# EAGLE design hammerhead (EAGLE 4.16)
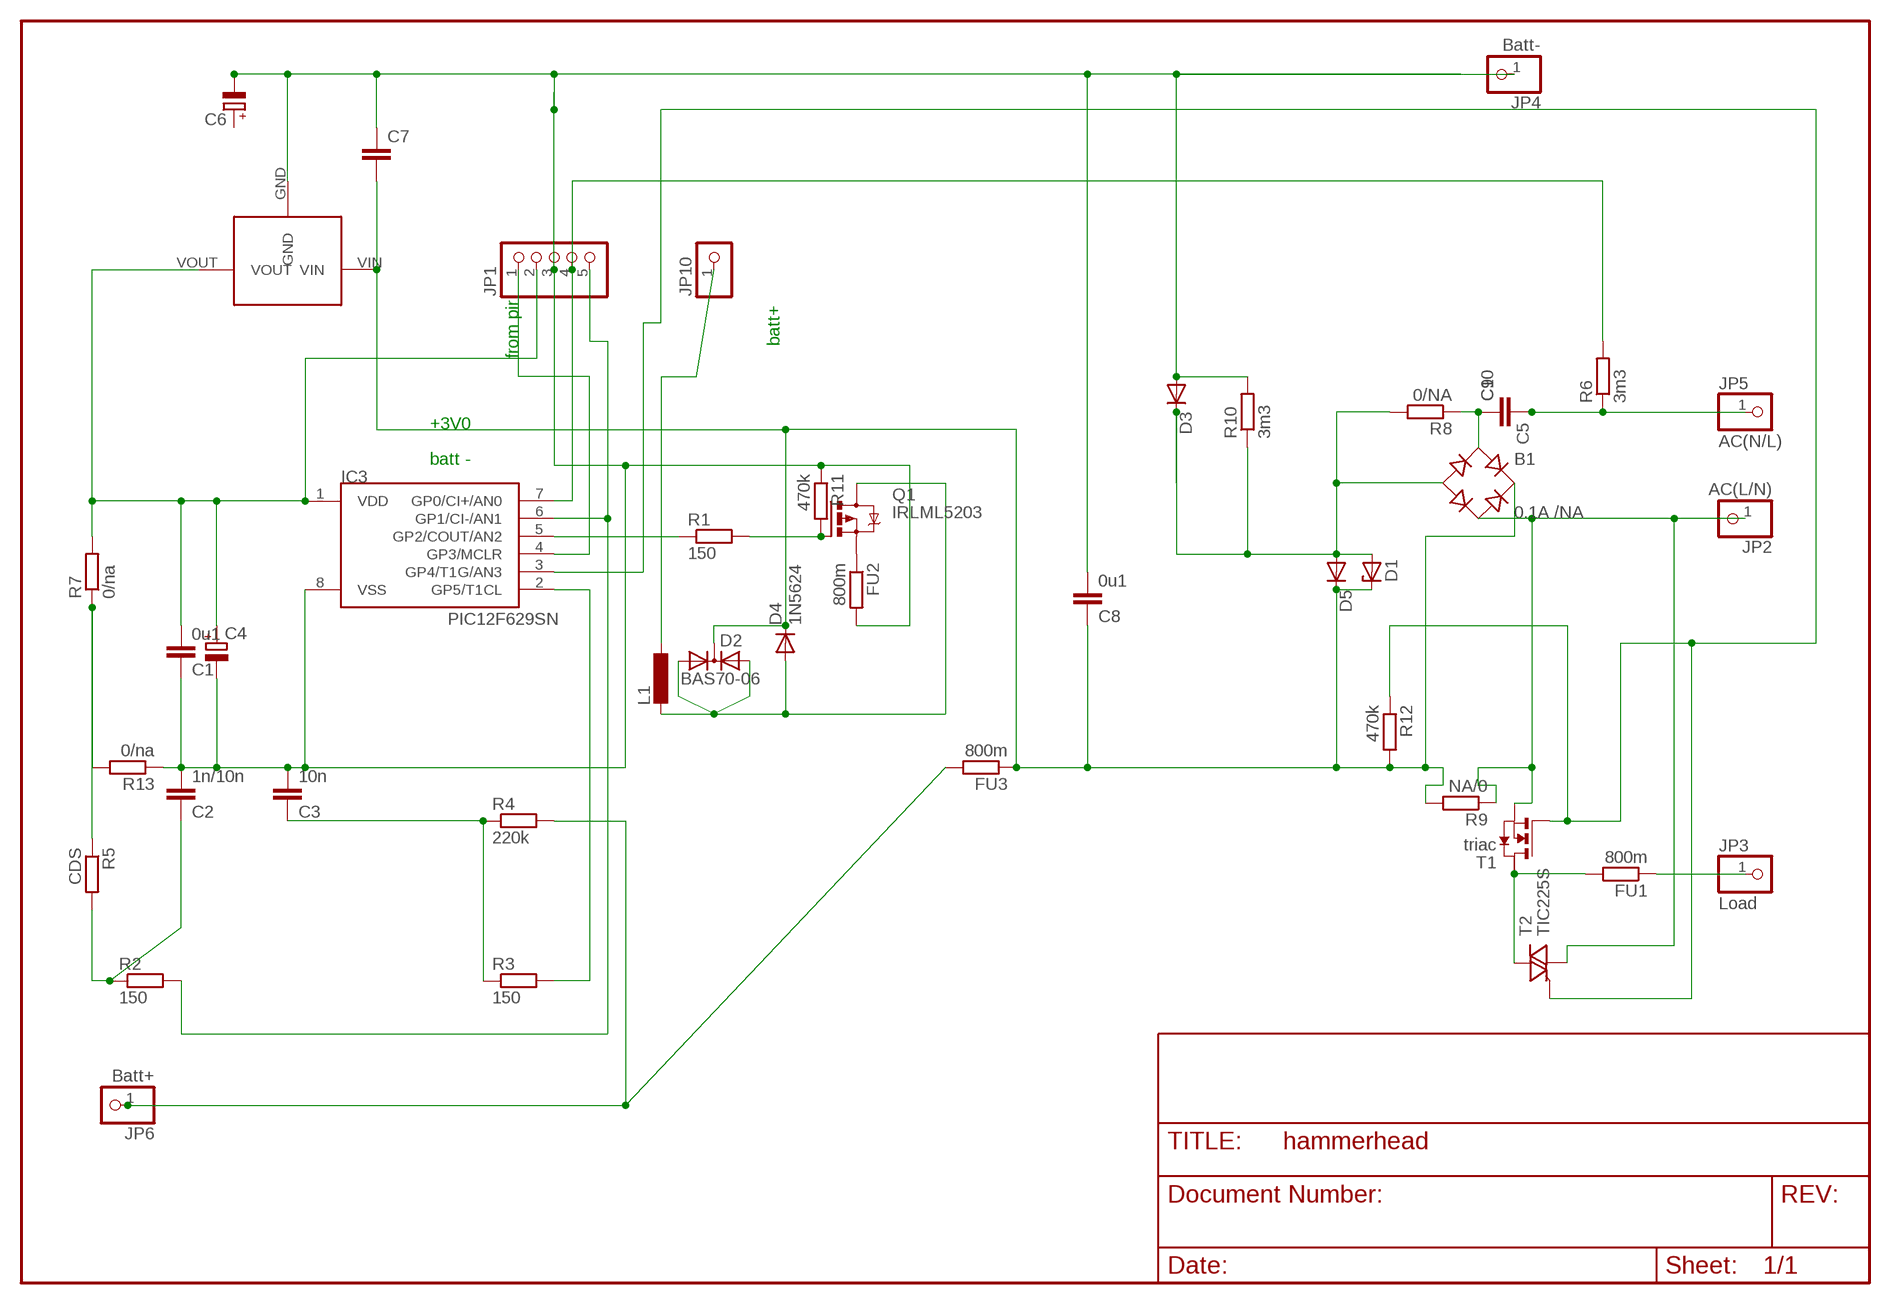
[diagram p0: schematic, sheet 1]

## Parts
B1  0.1A /NA  RECTIFIER-B40S  [B40S]
C1  0u1  C-EUC1206  [C1206]
C2  1n/10n  C-EUC1206  [C1206]
C3  10n  C-EUC1206  [C1206]
C4  CPOL-EUE2.5-6  [E2,5-6]
C5  C-EU050-025X075  [C050-025X075]
C6  CPOL-EUE2,5-6E  [E2,5-6E]
C7  C-EUC0805  [C0805]
C8  0u1  C-EUC1206  [C1206]
C9  C-EU075-032X103  [C075-032X103]
C10  C-EU102-043X133  [C102-043X133]
D1  ZENER-DIODESOT23  [SOT23]
D2  BAS70-06  [SOT23]
D3  DIODE-MELF-MLL41  [MELF-MLL41]
D4  1N5624  [DO201-15]
D5  DIODE-MINIMELF  [MINIMELF]
FU1  800m  R-EU_0204/5  [0204/5]
FU2  800m  R-EU_0204/5  [0204/5]
FU3  800m  R-EU_0204/5  [0204/5]
IC3  PIC12F629SN  [SO-08]
JP1  PINHD-1X5  [1X05]
JP2  AC(L/N)  PINHD-1X1  [1X01]
JP3  Load  PINHD-1X1  [1X01]
JP4  Batt-  PINHD-1X1  [1X01]
JP5  AC(N/L)  PINHD-1X1  [1X01]
JP6  Batt+  PINHD-1X1  [1X01]
JP10  PINHD-1X1  [1X01]
L1  L-EU2200-15.24  [2200-15.24]
Q1  IRLML5203  [MICRO3]
R1  150  R-EU_R0805  [R0805]
R2  150  R-EU_R0805  [R0805]
R3  150  R-EU_R0805  [R0805]
R4  220k  R-EU_R0805  [R0805]
R5  CDS  R-EU_0411/3V  [0411V]
R6  3m3  R-EU_R1206  [R1206]
R7  0/na  R-EU_R0402  [R0402]
R8  0/NA  R-EU_R0402  [R0402]
R9  NA/0  R-EU_R0402  [R0402]
R10  3m3  R-EU_R1206  [R1206]
R11  470k  R-EU_R0805  [R0805]
R12  470k  R-EU_R0805  [R0805]
R13  0/na  R-EU_R0402  [R0402]
T1  triac  NMOSSOT223  [SOT223]
T2  TIC225S  [TO220DS]
U$1  VREG-S  [TO92-S]

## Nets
GND: C1.1 C2.2 C3.2 C4.- C6.- C7.1 C8.2 D3.A FU2.2 IC3.8(VSS) JP1.3 JP4.1 R10.2 R11.1 R13.1 U$1.GND
N$2: IC3.6(GP1/CI-/AN1) JP1.5 R2.2
N$4: IC3.3(GP4/T1G/AN3) R12.1 T1.1(G) T2.G
N$5: D2.1(A1) D2.2(A2) D4.A L1.2 Q1.3(D)
N$6: C1.2 C4.+ IC3.1(VDD) JP1.2 R7.2 U$1.VOUT
N$7: C3.1 R3.1 R4.1
N$8: IC3.2(GP5/T1CL) R3.2
N$9: IC3.4(GP3/MCLR) JP1.1
N$11: C2.1 R2.1 R5.2
N$12: IC3.5(GP2/COUT/AN2) R1.1
N$14: IC3.7(GP0/CI+/AN0) JP1.4 R6.2
N$17: JP10.1 L1.1
N$18: FU1.1 JP3.1
N$19: FU1.2 T1.2(D) T2.A2
N$20: Q1.1(G) R1.2 R11.2
N$22: R5.1 R7.1 R13.2
N$23: B1.AC2 JP2.1 R9.1 T1.3(S) T2.A1
N$25: B1.- D1.1(A) D3.C D5.A R8.2 R10.1
N$26: B1.AC1 C5.2 C9.1 C10.1 R8.1
N$34: FU2.1 Q1.2(S)
N$36: FU3.2 JP6.1 R4.2
N$37: C5.1 C9.2 C10.2 JP5.1 R6.1
RECT+: B1.+ C7.2 C8.1 D1.3(C) D2.3(C) D4.C D5.C FU3.1 R9.2 R12.2 U$1.VIN
Unconnected: C6.+ T1.4(D2)

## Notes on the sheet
- batt+
- from pir
- +3V0
- batt -

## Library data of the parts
B1 = rectifier:RECTIFIER-: Rectifier
C1-C3 C5 C8-C10 = rcl:C-EU: CAPACITOR, European symbol
C4 C6 = rcl(2):CPOL-EU: POLARIZED CAPACITOR, European symbol
C7 = rcl(2):C-EU: CAPACITOR, European symbol
D1 = diode-1:ZENER-DIODE: Z-Diode
D2 = diode-1:BAS70-06: Silicon Schottky Diodes General-purpose diode for high-speed switching
D3 D5 = diode-1:DIODE-: DIODE
D4 = diode:1N5624: DIODE
FU1-FU3 R1-R13 = rcl:R-EU_: RESISTOR, European symbol
IC3 = microchip-3:PIC12F6*: uPC nW 1k Program Flash memory 2x Timer Comparator 10b A/D converter/ 4xIN
JP1 = pinhead(2):PINHD-1X5: PIN HEADER
JP2-JP6 = pinhead:PINHD-1X1: PIN HEADER
JP10 = pinhead(2):PINHD-1X1: PIN HEADER
L1 = rcl:L-EU: INDUCTOR, European symbol
Q1 = transistor-power:IRLML5203: HEXFET P-Channel Power MOSFET
T1 = zetex:NMOSSOT223: MOS FET
T2 = triac:TIC225S: TRIAC
U$1 = spoton:VREG-S: vreg aus spoton

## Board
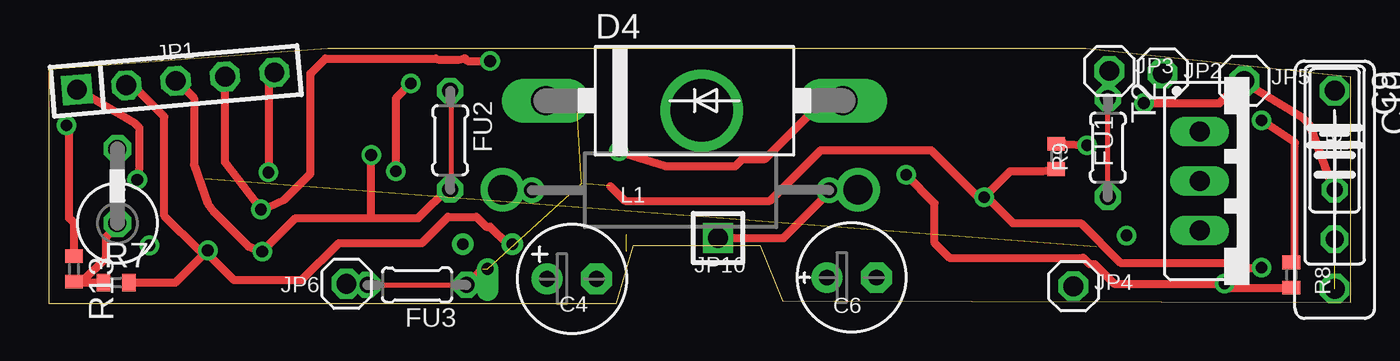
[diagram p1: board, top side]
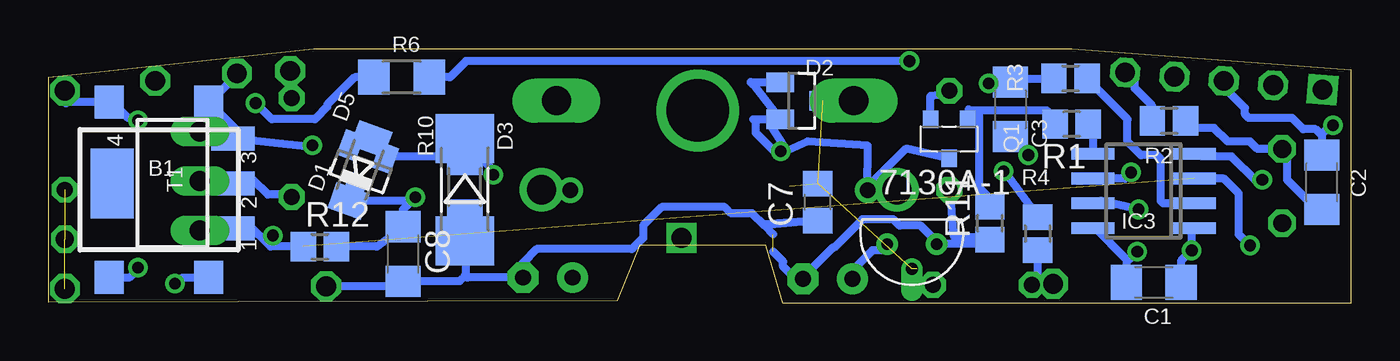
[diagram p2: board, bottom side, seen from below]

Size 66.76 x 13.08 mm. Coordinates in mm from the lower left corner, seen from the top.
Outline: 0,0 29.11,0 30,2.98 36.47,2.98 37.62,0.12 66.76,0.06 66.76,11.61 53.18,13.07 52.41,13.08 18,13.07 14.31,13.08 0,11.99 0,0
Copper layers (1*16): Top 0.035mm / dielectric 1.5mm / Bottom 0.035mm
Design rules "default": minimum track width 10mil, minimum drill 2mil, track to track 8mil, track to pad 8mil, pad to pad 8mil, via to via 8mil, smd to smd 8mil, copper to edge 1mil, drill to drill 8mil, minimum pad ring 10mil, minimum via ring 8mil, stop-mask expansion 4mil, vias tented up to drill 0mil, thermal gap 10mil

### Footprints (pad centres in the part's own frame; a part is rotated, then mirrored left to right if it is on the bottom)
B40S = smd 1.5 x 1.7: + -2.55,-4.5; - 2.55,-4.5; AC1 -2.55,4.5; AC2 2.55,4.5
C1206 = smd 1.6 x 1.8: 1 -1.4,0; 2 1.4,0
E2,5-6 = drill 0.813 pad 1.6 round: + -1.27,0 | drill 0.813 pad 1.6 octagon: - 1.27,0
C050-025X075 = drill 0.813 octagon: 1 -2.54,0; 2 2.54,0
E2,5-6E = drill 0.813 pad 1.575 round: + -1.27,0 | drill 0.813 pad 1.575 octagon: - 1.27,0
C0805 = smd 1.3 x 1.5: 1 -0.95,0; 2 0.95,0
C075-032X103 = drill 0.914 octagon: 1 -3.81,0; 2 3.81,0
C102-043X133 = drill 1.016 octagon: 1 -5.08,0; 2 5.08,0
SOT23 = smd 1 x 1.4: 1 -0.95,-1.1; 2 0.95,-1.1; 3 0,1.1
MELF-MLL41 = smd 2.5 x 3: A 2.625,0; C -2.625,0
DO201-15 = drill 1.499 long: A 7.62,0; C -7.62,0
MINIMELF = smd 1.4 x 1.8: A 1.7,0; C -1.7,0
0204/5 = drill 0.813 octagon: 1 -2.54,0; 2 2.54,0
SO-08 = smd 0.6 x 2.2: 1 -1.905,-2.6; 2 -0.635,-2.6; 3 0.635,-2.6; 4 1.905,-2.6; 5 1.905,2.6; 6 0.635,2.6; 7 -0.635,2.6; 8 -1.905,2.6
1X05 = drill 1.016 square: 1 -5.08,0 | drill 1.016 octagon: 2 -2.54,0; 3 0,0; 4 2.54,0; 5 5.08,0
1X01 = drill 1.016 octagon: 1 0,0
1X01' = drill 1.016 square: 1 0,0
2200-15.24 = drill 0.8 pad 1.27 round: 1 -7.62,0; 2 7.62,0
MICRO3 = smd 0.8 x 0.9: 1 -0.95,-1; 2 0.95,-1; 3 0,1
R0805 = smd 1.3 x 1.5: 1 -0.85,0; 2 0.85,0
0411V = drill 0.914 octagon: 1 -2.54,0; 2 1.27,0
R1206 = smd 1.6 x 1.803: 1 -1.422,0; 2 1.422,0
R0402 = smd 0.7 x 0.9: 1 -0.65,0; 2 0.65,0
SOT223 = smd 1.219 x 2.235: 1 -2.311,-3.099; 2 0,-3.099; 3 2.311,-3.099 | smd 3.6 x 2.2: 4 0,3.099
TO220DS = drill 1.016 long: A1 -2.54,-2.54; A2 0,-2.54; G 2.54,-2.54
TO92-S = drill 0.6 round: GND -2.54,0; VOUT 0,0 | drill 0.6 offset: VIN -1.27,1.27

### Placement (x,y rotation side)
B1  61.11,5.84 0 bottom
C1  10.11,1.09 0 bottom
C2  1.49,6.22 90 bottom
C3  17.45,9.96 270 bottom
C4  26.82,1.27 0 top
C5  65.94,8.38 90 top
C6  41.17,1.33 0 top
C7  27.33,5.2 90 bottom
C8  48.6,2.54 270 bottom
C9  65.94,7.11 270 top
C10  65.94,5.84 270 top
D1  50.77,6.77 160 bottom
D2  28.16,10.41 270 bottom
D3  45.43,5.84 270 bottom
D4  33.11,10.41 0 top
D5  50.8,6.86 70 bottom
FU1  54.31,8 270 top
FU2  20.58,8.38 270 top
FU3  18.89,0.95 180 top
IC3  10.63,5.77 90 bottom
JP1  6.51,11.42 5 top
JP2  57.11,11.81 0 top
JP3  54.38,11.93 0 top
JP4  52.54,0.88 0 top
JP5  61.3,11.42 0 top
JP6  15.27,1.01 0 top
JP10  [1X01']  34.32,3.36 0 top
L1  32.4,5.82 180 top
Q1  20.6,8.44 180 bottom
R1  14.31,9.2 180 bottom
R2  9.33,9.37 180 bottom
R3  14.38,11.55 0 bottom
R4  16.05,3.58 270 bottom
R5  3.52,6.66 90 top
R6  48.67,11.62 0 bottom
R7  3.45,1.07 0 top
R8  63.72,1.46 270 top
R9  51.65,7.55 270 top
R10  45.43,5.96 270 bottom
R11  18.5,4.12 90 bottom
R12  52.86,2.92 0 bottom
R13  1.3,1.77 270 top
T1  60.41,6.15 90 bottom
T2  61.56,6.28 270 top
U$1  23.77,3.04 180 bottom

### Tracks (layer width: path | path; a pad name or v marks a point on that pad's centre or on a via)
GND  (via drill 0.6)  (1 unrouted)
  Top 0.406: R13.1 1.3,4.12 1.04,4.38 1.04,9.01 v0.91,9.14 | 6.51,11.48 6.44,11.55 | JP1.3 6.51,11.48 | 6.51,11.48 7.45,10.54 7.45,7.11 8.15,5.14 8.47,4.69 10.25,2.92 v10.95,2.66 12.66,4.38 16.54,4.38 | FU2.2 20.58,6.01 18.95,4.38 16.54,4.38 | 16.54,4.38 v16.54,7.62
  Bottom 0.406: IC3.8 13.11,3.87 11.51,2.27 | 11.51,2.27 C1.1 | JP4.1 48.67,0.88 48.48,1.07 48.54,1.14 C8.2 45.69,1.14 45.4,1.42 | 45.4,1.42 45.36,1.46 45.36,3.11 45.47,3.21 | 45.47,3.21 45.49,3.23 | 45.47,3.21 D3.A 45.32,3.21 45.3,3.23 45.43,3.36 R10.2 | 45.4,1.42 45.43,1.46 | 45.4,1.42 | 45.4,1.42 45.3,1.33 C6.- 42.44,2.09 41.74,2.79 36.86,2.79 36.28,3.36 36.28,4 35.33,4.95 32.09,4.95 31.78,4.63 30.7,4.63 30.06,4 | C2.2 1.49,8.63 1.52,8.66 | 1.52,8.66 1.8,8.95 2.44,8.95 3.01,9.52 5.23,9.52 5.42,9.71 5.42,10.03 6.76,11.36 6.7,11.42 JP1.3 | 1.52,8.66 | v0.91,9.14 1.04,9.14 1.52,8.66 | 11.51,2.27 11.34,2.27 v10.95,2.66 10.95,2.73 11.26,2.41 | 18.5,3.42 R11.1 | 18.5,3.42 18.89,3.04 U$1.GND 21.17,3.11 22.06,4 23.14,4 23.46,4.31 25.04,4.31 26.51,2.85 26.57,2.85 28.09,1.33 C4.- 28.47,1.27 29.11,1.9 29.11,2.15 29.62,2.66 | C3.2 17.55,8.56 17.62,8.5 17.42,8.5 v16.54,7.62 | 18.5,3.42 20.35,3.42 20.41,3.68 20.54,5.46 20.6,5.96 20.58,5.95 FU2.2 | 30.12,4.06 | 30.12,4.06 C7.1 30.06,4 | 30.12,4.06 30.06,4 | 30.06,4 29.62,3.55
N$1
  Top 0.254: 54.19,10.47 54.32,10.47 54.32,5.46
N$2  (via drill 0.6)
  Top 0.406: JP1.5 11.59,11.86 11.65,11.81 11.26,11.42 v11.26,6.73
  Bottom 0.406: IC3.6 11.58,6.41 v11.26,6.73 | R2.2 10.18,10.14 11.07,11.04 11.07,11.42 11.52,11.87 11.53,11.86 JP1.5
N$3  (via drill 0.6)
  other vias: 55.27,3.49
N$4  (via drill 0.6)  (1 unrouted)
  Top 0.406: v5.17,2.98 5.23,2.98 5.3,2.92
  Bottom 0.406: IC3.3 6.5,6.41 5.74,5.65 5.74,3.55 v5.17,2.98 | T2.G 57.3,3.68 57.05,3.93 57.06,3.95 T1.1 56.52,4.03 55.4,2.92 R12.1
N$5  (via drill 0.6)
  Top 0.406: D4.A 39.71,10.41 36.73,7.42 35.59,7.42 35.2,7.04 31.65,7.04 v29.24,7.81
  Bottom 0.406: Q1.3 22.81,7.95 24.85,5.9 L1.2 24.77,8.1 27.84,8.31 29.36,7.62 30.51,8.76 30.51,9.33 30.64,9.46 D2.2 | 30.76,11.36 | 30.76,11.36 D2.1 | D2.2 30.65,11.25 30.76,11.36 | D2.2 29.7,9.05 29.11,8.12 v29.24,7.81
N$6  (via drill 0.6)
  Top 0.406: JP1.2 4.32,11.2 5.93,9.58 5.93,4.5 7.71,2.73 v8.15,2.73 | R7.2 6.5,1.07 v8.15,2.73 | U$1.VOUT 23.52,3.04 22.63,3.93 22.44,3.93 21.93,4.44 20.47,4.44 19.14,3.11 14.88,3.11 12.98,1.2 9.49,1.2 8.09,2.6 8.15,2.66 v8.15,2.73
  Bottom 0.406: IC3.1 8.03,3.8 8.15,3.68 v8.15,2.73 8.71,2.17 C1.2 | C4.+ 25.55,1.71 24.54,2.73 24.09,2.73 U$1.VOUT 23.65,3.17
N$7  (via drill 0.6)
  Top 0.406: v17.81,6.79 17.81,10.54 v18.57,11.3
  Bottom 0.406: R3.1 17.3,11.55 17.45,11.4 C3.1 17.45,11.53 | R4.1 17.67,6.65 v17.81,6.79 | 17.45,11.53 17.42,11.55 | v18.57,11.3 17.68,11.3 17.45,11.53
N$8
  Bottom 0.406: IC3.2 9.61,5.14 9.74,5.27 9.74,7.42 9.93,7.62 10.76,7.62 11.46,8.31 11.46,9.46 13.53,11.53 R3.2
N$9  (via drill 0.6)
  Top 0.406: JP1.1 4.43,9.24 4.66,9.01 4.66,6.98 v4.53,6.34
  Bottom 0.406: v4.53,6.34 4.85,6.28 6.12,7.55 7.65,7.55 7.77,7.68 IC3.4
N$11
  Bottom 0.406: C2.1 1.74,4.82 3.26,6.34 3.26,7.68 R5.2 4.79,7.93 5.17,8.31 6.31,8.31 7.01,9.01 8.09,9.01 8.45,9.37 R2.1
N$12
  Bottom 0.406: R1.1 13.49,9.2 13.55,9.14 13.23,8.82 IC3.5
N$14  (via drill 0.6)
  Top 0.406: JP1.4 9.04,7.24 v10.88,4.82 10.95,4.82 11.26,4.95 12.09,5.33 13.42,6.66 13.42,11.81 14.19,12.57 19.84,12.57 20.03,12.5 20.98,12.5 21.3,12.57 21.36,12.57 21.49,12.44 v22.63,12.44
  Bottom 0.406: IC3.7 12.92,5.14 12.79,5.27 v10.88,4.82 | R6.2 46.19,11.61 45.36,12.44 v22.63,12.44
N$15  (via drill 1.5)
  other vias: 41.49,5.84
N$16  (via drill 1.5)
  other vias: 23.27,5.84
N$17
  Top 0.406: L1.1 40.05,5.82 40.09,5.77 37.68,3.36 JP10.1
  Bottom 0.406: L1.1 39.99,5.82
N$18
  Bottom 0.406: JP3.1 54.38,11.81 54.31,11.73 FU1.1
N$19
  Bottom 0.406: FU1.2 54.31,5.51 54.38,5.58 55.52,5.58 56.29,6.34 T1.2 58.7,6.34 58.83,6.22 T2.A2
N$20
  Bottom 0.406: R1.2 15.16,9.48 15.58,9.9 19.14,9.9 | Q1.1 19.6,9.95 19.58,9.96 19.52,9.9 19.14,9.9 | R11.2 18.5,5.39 19.08,5.96 19.08,9.84 19.14,9.9
N$22
  Top 0.406: R7.1 1.42,1.07 1.37,1.12 R13.2 1.73,1.12 2.95,2.34 2.95,3.42 3.52,4 R5.1
N$23  (via drill 0.6)
  Top 0.406: v53.24,8.12 52.03,8.19 51.95,8.3 R9.1
  Bottom 0.406: JP2.1 57.05,11.81 58.52,10.34 B1.AC2 57.18,8.95 57.18,8.69 57.14,8.66 T1.3 | T1.3 53.34,8.02 v53.24,8.12 | T1.3 57.26,8.66 57.37,8.76 T2.A1
N$24
  Top 0.254: 16.66,0.95 21.36,0.95
N$25  (via drill 0.6)
  Top 0.406: R8.2 60.49,0.81 v60.29,1.01 54.64,1.01 53.62,2.03 53.37,2.03 53.05,2.34 46.19,2.34 45.43,3.11 45.43,5.14 v43.97,6.6
  Bottom 0.406: B1.- 59.9,1.34 v60.29,1.01 | R10.1 45.43,7.49 45.49,7.55 | 45.49,7.55 45.49,8.31 45.43,8.38 D3.C 45.43,8.31 43.97,6.85 v43.97,6.6 | 45.49,7.55 49.37,7.55 49.43,7.62 49.5,7.55 D1.1 49.5,7.75 50.22,8.47 | 50.22,8.47 50.25,8.5 | 50.22,8.47 D5.A
N$26  (via drill 0.6)
  Top 0.406: R8.1 63.6,2.11 63.91,2.09 63.91,8.25 v62.19,9.39
  Bottom 0.406: v62.19,9.39 62.7,9.52 63.53,10.35 63.53,10.34 B1.AC1 65.82,10.34 65.88,10.28 C10.1
N$27
  Top 0.254: 20.66,6.03 20.66,10.79
N$28  (via drill 3.2)
  other vias: 33.49,9.9
N$34
  Bottom 0.406: FU2.1 20.77,10.84 21.11,10.73 21.55,10.67 Q1.2
N$36
  Bottom 0.406: 16.05,1.24 R4.2 | FU3.2 16.05,1.24 | JP6.1 15.58,1.01 15.81,1.24 16.05,1.24
N$37  (via drill 0.6)  (2 unrouted)
  Top 0.406: C5.1 65.68,6.34 64.67,9.14 64.22,9.58 61.3,11.36 JP5.1 61.18,11.42 60.03,10.28 v56.16,10.28
  Bottom 0.406: R6.1 51.08,11.61 52.48,10.22 52.48,10.09 53.11,9.46 55.33,9.46 v56.16,10.28
RECT+  (via drill 0.6)  (4 unrouted)
  Top 0.406: R9.2 50.95,6.79 49.3,6.79 v47.97,5.46 | FU3.1 22.25,1.77 | v62.19,1.84 61.3,1.84 61.05,2.09 54.95,2.09 52.92,4.12 49.43,4.12 48.09,5.46 v47.97,5.46 | v47.97,5.46 47.65,5.46 45.24,7.87 39.59,7.87 36.98,5.27 29.55,5.27 28.79,6.03
  Bottom 0.406: D4.C 25.55,10.47 25.62,10.41 D2.3 | R12.2 49.94,2.92 C8.1 | C8.1 | 63.66,1.32 B1.+ | 63.66,1.32 63.72,1.27 | C8.1 48.6,4.82 v47.97,5.46 48.03,5.46 48.22,5.26 D5.C 51.39,5.91 51.14,6.16 51.14,6.15 D1.3 | 63.66,1.32 62.65,1.32 62.32,1.65 62.32,1.71 v62.19,1.84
